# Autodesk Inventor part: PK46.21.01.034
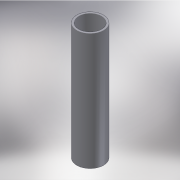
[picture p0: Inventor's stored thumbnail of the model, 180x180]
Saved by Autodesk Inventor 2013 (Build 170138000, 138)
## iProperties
Created: 2005-04
Part Number: PK46.21.01.034
Material: Steel, Mild
Document SubType Name: Modeling
Designer: salex
Manufacturer: Standard
Standards Organization: Custom
Density: 7.86 g/cm^3
Author: salex
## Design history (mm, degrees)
sketch "Эскиз1"
  geometry: C1 r 25 at (0, 0); C2 r 21.5 at (0, 0)
  constraints: 2 centre point, 1 coincident, 1 other
  dimensions: "d0" = 50 diameter of C1; "d1" = 3.5 radial gap between concentric circles of C1 C2
extrude "Выдавливание1" new body sketch "Эскиз1" distance "d2" = 220; taper "d3" = 0 deg
body "Solid1"
